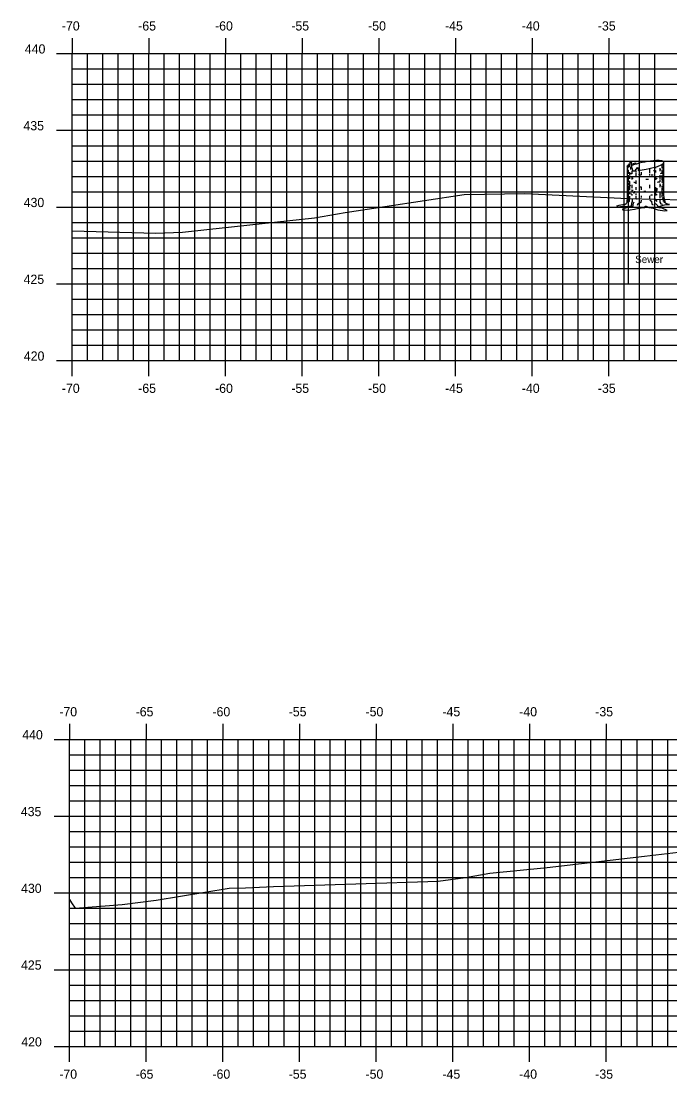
# Model space of a CAD drawing. Extents: x -161 to 764, y 111 to 210.
# Drawn here: x -161 to -118.7, y 131.7 to 200.5 of the extents above; entities that cross this region are included whole.
import ezdxf

# ---------------------------------------------------------------- set-up
doc = ezdxf.new("R2010")
doc.units = 0
for name, color, linetype in [('H_V ANNOTATION', 7, 'Continuous'), ('MAJOR', 7, 'Continuous'), ('MINOR', 7, 'Continuous'), ('S_Roadway_Centerline', 7, 'Continuous'), ('S_Trees_Decid_Pay', 7, 'Continuous'), ('S_Utilities_UG_Sanitary_Sewer', 7, 'Continuous')]:
    doc.layers.add(name, color=color, linetype=linetype)

msp = doc.modelspace()

# ---------------------------------------------------------------- linework, layer by layer
at = {"layer": 'MAJOR'}
for p, q in [((-157.693, 199.435), (-157.693, 198.433)), ((-152.693, 199.435), (-152.693, 198.433)), ((-147.693, 199.435), (-147.693, 198.433)), ((-142.693, 199.435), (-142.693, 198.433)), ((-137.693, 199.435), (-137.693, 198.433)), ((-132.693, 199.435), (-132.693, 198.433)), ((-127.693, 199.435), (-127.693, 198.433)), ((-122.693, 199.435), (-122.693, 198.433)), ((-158.695, 198.433), (-157.693, 198.433)), ((-157.693, 198.433), (-17.693, 198.433)), ((-157.693, 178.433), (-157.693, 198.433)), ((-157.693, 178.433), (-157.693, 198.433)), ((-157.693, 198.433), (-17.693, 198.433)), ((-152.693, 178.433), (-152.693, 198.433)), ((-147.693, 178.433), (-147.693, 198.433)), ((-142.693, 178.433), (-142.693, 198.433)), ((-137.693, 178.433), (-137.693, 198.433)), ((-132.693, 178.433), (-132.693, 198.433)), ((-127.693, 178.433), (-127.693, 198.433)), ((-122.693, 178.433), (-122.693, 198.433)), ((-158.695, 193.433), (-157.693, 193.433)), ((-157.693, 193.433), (-17.693, 193.433)), ((-158.695, 188.433), (-157.693, 188.433)), ((-157.693, 188.433), (-17.693, 188.433)), ((-158.695, 183.433), (-157.693, 183.433)), ((-157.693, 183.433), (-17.693, 183.433)), ((-158.695, 178.433), (-157.693, 178.433)), ((-157.693, 178.433), (-17.693, 178.433)), ((-157.693, 178.433), (-17.693, 178.433)), ((-157.693, 177.431), (-157.693, 178.433)), ((-152.693, 177.431), (-152.693, 178.433)), ((-147.693, 177.431), (-147.693, 178.433)), ((-142.693, 177.431), (-142.693, 178.433)), ((-137.693, 177.431), (-137.693, 178.433)), ((-132.693, 177.431), (-132.693, 178.433)), ((-127.693, 177.431), (-127.693, 178.433)), ((-122.693, 177.431), (-122.693, 178.433)), ((-157.863, 154.77), (-157.863, 153.768)), ((-152.863, 154.77), (-152.863, 153.768)), ((-147.863, 154.77), (-147.863, 153.768)), ((-142.863, 154.77), (-142.863, 153.768)), ((-137.863, 154.77), (-137.863, 153.768)), ((-132.863, 154.77), (-132.863, 153.768)), ((-127.863, 154.77), (-127.863, 153.768)), ((-122.863, 154.77), (-122.863, 153.768)), ((-158.865, 153.768), (-157.863, 153.768)), ((-157.863, 153.768), (-17.863, 153.768)), ((-157.863, 133.768), (-157.863, 153.768)), ((-157.863, 133.768), (-157.863, 153.768)), ((-157.863, 153.768), (-17.863, 153.768)), ((-152.863, 133.768), (-152.863, 153.768)), ((-147.863, 133.768), (-147.863, 153.768)), ((-142.863, 133.768), (-142.863, 153.768)), ((-137.863, 133.768), (-137.863, 153.768)), ((-132.863, 133.768), (-132.863, 153.768)), ((-127.863, 133.768), (-127.863, 153.768)), ((-122.863, 133.768), (-122.863, 153.768)), ((-158.865, 148.768), (-157.863, 148.768)), ((-157.863, 148.768), (-17.863, 148.768)), ((-158.865, 143.768), (-157.863, 143.768)), ((-157.863, 143.768), (-17.863, 143.768)), ((-158.865, 138.768), (-157.863, 138.768)), ((-157.863, 138.768), (-17.863, 138.768)), ((-158.865, 133.768), (-157.863, 133.768)), ((-157.863, 133.768), (-17.863, 133.768)), ((-157.863, 133.768), (-17.863, 133.768)), ((-157.863, 132.766), (-157.863, 133.768)), ((-152.863, 132.766), (-152.863, 133.768)), ((-147.863, 132.766), (-147.863, 133.768)), ((-142.863, 132.766), (-142.863, 133.768)), ((-137.863, 132.766), (-137.863, 133.768)), ((-132.863, 132.766), (-132.863, 133.768)), ((-127.863, 132.766), (-127.863, 133.768)), ((-122.863, 132.766), (-122.863, 133.768))]:
    msp.add_line(p, q, dxfattribs=at)
at = {"layer": 'MINOR'}
for p, q in [((-156.693, 178.433), (-156.693, 198.433)), ((-155.693, 178.433), (-155.693, 198.433)), ((-154.693, 178.433), (-154.693, 198.433)), ((-153.693, 178.433), (-153.693, 198.433)), ((-151.693, 178.433), (-151.693, 198.433)), ((-150.693, 178.433), (-150.693, 198.433)), ((-149.693, 178.433), (-149.693, 198.433)), ((-148.693, 178.433), (-148.693, 198.433)), ((-146.693, 178.433), (-146.693, 198.433)), ((-145.693, 178.433), (-145.693, 198.433)), ((-144.693, 178.433), (-144.693, 198.433)), ((-143.693, 178.433), (-143.693, 198.433)), ((-141.693, 178.433), (-141.693, 198.433)), ((-140.693, 178.433), (-140.693, 198.433)), ((-139.693, 178.433), (-139.693, 198.433)), ((-138.693, 178.433), (-138.693, 198.433)), ((-136.693, 178.433), (-136.693, 198.433)), ((-135.693, 178.433), (-135.693, 198.433)), ((-134.693, 178.433), (-134.693, 198.433)), ((-133.693, 178.433), (-133.693, 198.433)), ((-131.693, 178.433), (-131.693, 198.433)), ((-130.693, 178.433), (-130.693, 198.433)), ((-129.693, 178.433), (-129.693, 198.433)), ((-128.693, 178.433), (-128.693, 198.433)), ((-126.693, 178.433), (-126.693, 198.433)), ((-125.693, 178.433), (-125.693, 198.433)), ((-124.693, 178.433), (-124.693, 198.433)), ((-123.693, 178.433), (-123.693, 198.433)), ((-121.693, 178.433), (-121.693, 198.433)), ((-120.693, 178.433), (-120.693, 198.433)), ((-119.693, 178.433), (-119.693, 198.433)), ((-157.693, 197.433), (-17.693, 197.433)), ((-157.693, 197.433), (-156.691, 197.433)), ((-157.693, 196.433), (-17.693, 196.433)), ((-157.693, 196.433), (-156.691, 196.433)), ((-157.693, 195.433), (-17.693, 195.433)), ((-157.693, 195.433), (-156.691, 195.433)), ((-157.693, 194.433), (-17.693, 194.433)), ((-157.693, 194.433), (-156.691, 194.433)), ((-157.693, 192.433), (-17.693, 192.433)), ((-157.693, 192.433), (-156.691, 192.433)), ((-157.693, 191.433), (-17.693, 191.433)), ((-157.693, 191.433), (-156.691, 191.433)), ((-157.693, 190.433), (-17.693, 190.433)), ((-157.693, 190.433), (-156.691, 190.433)), ((-157.693, 189.433), (-17.693, 189.433)), ((-157.693, 189.433), (-156.691, 189.433)), ((-157.693, 187.433), (-17.693, 187.433)), ((-157.693, 187.433), (-156.691, 187.433)), ((-157.693, 186.433), (-17.693, 186.433)), ((-157.693, 186.433), (-156.691, 186.433)), ((-157.693, 185.433), (-17.693, 185.433)), ((-157.693, 185.433), (-156.691, 185.433)), ((-157.693, 184.433), (-17.693, 184.433)), ((-157.693, 184.433), (-156.691, 184.433)), ((-157.693, 182.433), (-17.693, 182.433)), ((-157.693, 182.433), (-156.691, 182.433)), ((-157.693, 181.433), (-17.693, 181.433)), ((-157.693, 181.433), (-156.691, 181.433)), ((-157.693, 180.433), (-17.693, 180.433)), ((-157.693, 180.433), (-156.691, 180.433)), ((-157.693, 179.433), (-17.693, 179.433)), ((-157.693, 179.433), (-156.691, 179.433)), ((-156.863, 133.768), (-156.863, 153.768)), ((-155.863, 133.768), (-155.863, 153.768)), ((-154.863, 133.768), (-154.863, 153.768)), ((-153.863, 133.768), (-153.863, 153.768)), ((-151.863, 133.768), (-151.863, 153.768)), ((-150.863, 133.768), (-150.863, 153.768)), ((-149.863, 133.768), (-149.863, 153.768)), ((-148.863, 133.768), (-148.863, 153.768)), ((-146.863, 133.768), (-146.863, 153.768)), ((-145.863, 133.768), (-145.863, 153.768)), ((-144.863, 133.768), (-144.863, 153.768)), ((-143.863, 133.768), (-143.863, 153.768)), ((-141.863, 133.768), (-141.863, 153.768)), ((-140.863, 133.768), (-140.863, 153.768)), ((-139.863, 133.768), (-139.863, 153.768)), ((-138.863, 133.768), (-138.863, 153.768)), ((-136.863, 133.768), (-136.863, 153.768)), ((-135.863, 133.768), (-135.863, 153.768)), ((-134.863, 133.768), (-134.863, 153.768)), ((-133.863, 133.768), (-133.863, 153.768)), ((-131.863, 133.768), (-131.863, 153.768)), ((-130.863, 133.768), (-130.863, 153.768)), ((-129.863, 133.768), (-129.863, 153.768)), ((-128.863, 133.768), (-128.863, 153.768)), ((-126.863, 133.768), (-126.863, 153.768)), ((-125.863, 133.768), (-125.863, 153.768)), ((-124.863, 133.768), (-124.863, 153.768)), ((-123.863, 133.768), (-123.863, 153.768)), ((-121.863, 133.768), (-121.863, 153.768)), ((-120.863, 133.768), (-120.863, 153.768)), ((-119.863, 133.768), (-119.863, 153.768)), ((-118.863, 133.768), (-118.863, 153.768)), ((-157.863, 152.768), (-17.863, 152.768)), ((-157.863, 152.768), (-156.861, 152.768)), ((-157.863, 151.768), (-17.863, 151.768)), ((-157.863, 151.768), (-156.861, 151.768)), ((-157.863, 150.768), (-17.863, 150.768)), ((-157.863, 150.768), (-156.861, 150.768)), ((-157.863, 149.768), (-17.863, 149.768)), ((-157.863, 149.768), (-156.861, 149.768)), ((-157.863, 147.768), (-17.863, 147.768)), ((-157.863, 147.768), (-156.861, 147.768)), ((-157.863, 146.768), (-17.863, 146.768)), ((-157.863, 146.768), (-156.861, 146.768)), ((-157.863, 145.768), (-17.863, 145.768)), ((-157.863, 145.768), (-156.861, 145.768)), ((-157.863, 144.768), (-17.863, 144.768)), ((-157.863, 144.768), (-156.861, 144.768)), ((-157.863, 142.768), (-17.863, 142.768)), ((-157.863, 142.768), (-156.861, 142.768)), ((-157.863, 141.768), (-17.863, 141.768)), ((-157.863, 141.768), (-156.861, 141.768)), ((-157.863, 140.768), (-17.863, 140.768)), ((-157.863, 140.768), (-156.861, 140.768)), ((-157.863, 139.768), (-17.863, 139.768)), ((-157.863, 139.768), (-156.861, 139.768)), ((-157.863, 137.768), (-17.863, 137.768)), ((-157.863, 137.768), (-156.861, 137.768)), ((-157.863, 136.768), (-17.863, 136.768)), ((-157.863, 136.768), (-156.861, 136.768)), ((-157.863, 135.768), (-17.863, 135.768)), ((-157.863, 135.768), (-156.861, 135.768)), ((-157.863, 134.768), (-17.863, 134.768)), ((-157.863, 134.768), (-156.861, 134.768))]:
    msp.add_line(p, q, dxfattribs=at)
at = {"layer": 'S_Roadway_Centerline'}
for points in [[(-157.693, 186.896), (-152.22, 186.735), (-150.498, 186.807), (-148.901, 186.975), (-141.893, 187.734), (-139.882, 188.09), (-132.124, 189.256), (-128.171, 189.315), (-121.467, 188.992), (-115.974, 188.872), (-110.769, 188.6), (-96.239, 188.433), (-93.99, 188.538), (-87.1, 188.918), (-86.065, 188.968), (-75.289, 189.172), (-68.973, 189.373), (-42.532, 188.98), (-34.493, 188.828), (-32.191, 188.81), (-29.47, 188.805), (-17.693, 188.431)], [(-157.863, 143.341), (-157.723, 143.12), (-157.491, 142.781), (-154.413, 143.007), (-152.205, 143.302), (-147.459, 144.078), (-146.374, 144.11), (-144.561, 144.195), (-133.827, 144.541), (-132.039, 144.763), (-130.463, 145.049), (-126.715, 145.433), (-120.377, 146.165), (-117.425, 146.515), (-117.256, 146.518), (-109.618, 146.417), (-104.371, 146.317), (-104.168, 146.321), (-87.565, 146.329), (-83.22, 146.326), (-80.412, 146.295), (-73.107, 146.205)]]:
    msp.add_lwpolyline(points, dxfattribs=at)
at = {"layer": 'S_Trees_Decid_Pay'}
for p, q in [((-121.446, 190.854), (-121.446, 190.599)), ((-121.296, 191.054), (-121.296, 190.88)), ((-121.211, 190.805), (-121.211, 190.601)), ((-120.95, 190.807), (-120.95, 190.688)), ((-120.039, 190.945), (-120.039, 190.665)), ((-119.656, 191.046), (-119.656, 190.96)), ((-119.656, 190.819), (-119.656, 190.679)), ((-119.384, 190.96), (-119.384, 190.768)), ((-119.251, 191.213), (-119.251, 190.96)), ((-119.251, 190.863), (-119.251, 190.599)), ((-119.171, 191.258), (-119.171, 191.137)), ((-119.171, 191.085), (-119.171, 190.871)), ((-119.171, 190.826), (-119.171, 190.488)), ((-121.446, 190.502), (-121.446, 190.033)), ((-121.36, 190.708), (-121.36, 190.496)), ((-121.36, 190.431), (-121.36, 190.282)), ((-121.211, 190.393), (-121.211, 190.239)), ((-120.95, 190.636), (-120.95, 190.451)), ((-120.95, 190.165), (-120.95, 189.937)), ((-120.712, 190.536), (-120.707, 190.643)), ((-120.585, 190.708), (-120.585, 190.529)), ((-120.039, 190.599), (-120.039, 190.496)), ((-119.656, 190.393), (-119.656, 190.202)), ((-119.384, 190.517), (-119.384, 190.239)), ((-119.384, 190.194), (-119.384, 190.085)), ((-119.251, 190.502), (-119.251, 190.194)), ((-119.171, 190.371), (-119.171, 190.01)), ((-121.446, 189.982), (-121.446, 189.848)), ((-121.446, 189.79), (-121.446, 189.465)), ((-121.446, 189.436), (-121.446, 189.016)), ((-121.36, 190.105), (-121.36, 189.805)), ((-121.36, 189.767), (-121.36, 189.525)), ((-121.211, 189.876), (-121.211, 189.657)), ((-121.211, 189.557), (-121.211, 189.436)), ((-120.95, 189.739), (-120.95, 189.553)), ((-120.585, 189.75), (-120.585, 189.553)), ((-120.039, 189.885), (-120.039, 189.664)), ((-119.656, 189.722), (-119.656, 189.514)), ((-119.384, 189.95), (-119.384, 189.722)), ((-119.251, 190.105), (-119.251, 190.039)), ((-119.251, 189.805), (-119.251, 189.708)), ((-119.251, 189.657), (-119.251, 189.296)), ((-119.171, 189.973), (-119.171, 189.525)), ((-119.171, 189.459), (-119.171, 189.177)), ((-121.442, 188.913), (-121.457, 188.796)), ((-121.36, 189.414), (-121.36, 189.273)), ((-121.36, 189.141), (-121.36, 188.985)), ((-121.211, 189.285), (-121.211, 189.187)), ((-120.95, 189.319), (-120.95, 189.242)), ((-120.95, 189.164), (-120.95, 188.991)), ((-120.585, 189.17), (-120.585, 189.067)), ((-120.039, 189.164), (-120.039, 188.991)), ((-119.661, 188.936), (-119.581, 188.804)), ((-119.656, 189.393), (-119.656, 189.193)), ((-119.384, 189.393), (-119.384, 189.01)), ((-119.251, 189.244), (-119.251, 189.078))]:
    msp.add_line(p, q, dxfattribs=at)
for points in [[(-121.496, 191.128), (-121.496, 188.991), (-121.516, 188.849), (-121.522, 188.723), (-121.566, 188.637), (-121.658, 188.588), (-121.794, 188.588), (-122.037, 188.532), (-122.204, 188.483), (-122.062, 188.452), (-121.825, 188.489), (-121.615, 188.477), (-121.354, 188.483), (-121.23, 188.501), (-121.2, 188.458), (-121.137, 188.501), (-121.236, 188.433), (-121.471, 188.408), (-121.701, 188.347), (-121.831, 188.277), (-121.732, 188.233), (-121.31, 188.252), (-121.032, 188.296), (-120.734, 188.372), (-120.448, 188.408), (-120.343, 188.408), (-120.324, 188.489), (-120.256, 188.495), (-120.089, 188.408), (-119.803, 188.353), (-119.505, 188.246), (-119.045, 188.197), (-118.891, 188.209), (-119.233, 188.359), (-119.436, 188.39), (-119.425, 188.464), (-119.165, 188.563), (-118.99, 188.594), (-118.749, 188.606), (-118.947, 188.643), (-119.009, 188.68), (-119.033, 188.767), (-119.045, 188.936), (-119.091, 189.022), (-119.119, 189.263), (-119.119, 191.349)], [(-121.14, 190.801), (-121.148, 190.945), (-121.193, 190.937), (-121.207, 191.312), (-121.302, 191.32), (-121.316, 191.4), (-121.354, 191.063), (-121.399, 191.157), (-121.419, 191.003), (-121.496, 191.128), (-121.49, 190.939)], [(-121.496, 191.128), (-121.45, 191.151), (-121.428, 191.217), (-121.376, 191.24), (-121.343, 191.165)], [(-121.117, 191.167), (-121.096, 191.275), (-120.965, 191.305), (-120.957, 191.218)], [(-120.978, 190.805), (-120.942, 190.908), (-120.876, 190.914), (-120.876, 190.996), (-120.802, 191.003), (-120.777, 190.823)], [(-121.088, 189.436), (-121.096, 189.362), (-121.022, 189.356), (-121.008, 189.473)], [(-119.543, 189.528), (-119.544, 189.605), (-119.552, 189.671)], [(-121.376, 188.921), (-121.383, 188.796), (-121.465, 188.701)], [(-121.23, 188.501), (-121.211, 188.68), (-121.15, 188.817), (-121.156, 188.917)], [(-121.039, 188.748), (-121.113, 188.68), (-121.131, 188.582), (-121.137, 188.501)], [(-120.587, 188.884), (-120.604, 188.73), (-120.802, 188.649), (-120.847, 188.546)], [(-120.022, 188.876), (-119.919, 188.824), (-119.904, 188.618), (-119.801, 188.59)], [(-119.367, 188.95), (-119.367, 188.744), (-119.309, 188.635), (-119.212, 188.618)], [(-119.226, 189.024), (-119.155, 188.921), (-119.155, 188.796)], [(-119.169, 189.105), (-119.109, 188.944), (-119.095, 188.819), (-119.103, 188.721)], [(-119.436, 188.39), (-119.523, 188.532), (-119.655, 188.674)]]:
    msp.add_lwpolyline(points, dxfattribs=at)
for centre, radius, start, end in [((-120.686, 189.941), 1.299, 107.86134, 113.3069), ((-119.206, 185.347), 6.126, 100.77788, 107.86134), ((-121.408, 196.916), 6.126, 273.69441, 274.02462), ((-121.408, 196.916), 6.126, 275.91473, 280.77788), ((-119.206, 185.347), 6.126, 93.69441, 100.77788), ((-121.408, 196.916), 6.126, 280.77788, 287.86134), ((-120.306, 196.699), 5.916, 274.95145, 276.30875), ((-119.517, 190.164), 1.299, 78.27788, 93.69441), ((-119.928, 192.322), 1.299, 287.86134, 303.27788), ((-119.73, 192.111), 1.292, 285.56512, 289.09156), ((-119.351, 190.966), 0.48, 69.98432, 78.27788), ((-119.478, 191.637), 0.48, 303.27788, 311.57144), ((-119.243, 191.263), 0.164, 55.77788, 69.98432), ((-119.258, 191.092), 0.166, 301.67004, 315), ((-119.269, 191.401), 0.164, 311.57144, 325.77788), ((-119.211, 191.31), 0.107, 45.9547, 55.77788), ((-119.218, 191.051), 0.109, 315, 324.82628), ((-119.181, 191.34), 0.0645, 33.27788, 45.9547), ((-119.222, 191.369), 0.107, 325.77788, 335.60106), ((-119.182, 191.026), 0.0657, 324.82628, 337.5), ((-119.173, 191.346), 0.0544, 22.46002, 33.27788), ((-119.183, 191.351), 0.0645, 335.60106, 348.27788), ((-119.165, 191.349), 0.0467, 10.77788, 22.46002), ((-119.173, 191.022), 0.0554, 337.5, 348.31854), ((-119.173, 191.349), 0.0544, 348.27788, 359.09574), ((-119.165, 191.349), 0.0467, 359.09574, 10.77788), ((-121.448, 190.76), 0.0476, 180, 191.68146), ((-121.448, 190.239), 0.0476, 180, 191.68146), ((-121.441, 190.762), 0.0554, 191.68146, 202.5), ((-121.441, 190.241), 0.0554, 191.68146, 202.5), ((-121.431, 190.765), 0.0657, 202.5, 215.17372), ((-121.431, 190.245), 0.0657, 202.5, 215.17372), ((-121.396, 190.79), 0.109, 215.17372, 225), ((-121.396, 190.27), 0.109, 215.17372, 225), ((-121.355, 190.831), 0.166, 225, 239.19244), ((-121.355, 190.31), 0.166, 225, 239.19244), ((-121.355, 190.567), 0.166, 237.03779, 239.19244), ((-121.192, 190.84), 0.484, 239.19244, 247.5), ((-121.192, 190.583), 0.484, 239.19244, 245.77245), ((-120.883, 191.587), 1.292, 247.5, 248.35373), ((-120.883, 191.329), 1.292, 247.5, 248.48417), ((-120.883, 191.85), 1.292, 250.61187, 255.28558), ((-120.883, 191.587), 1.292, 255.28558, 259.26323), ((-121.097, 192.1), 1.299, 268.12894, 273.69441), ((-120.307, 196.438), 5.916, 266.07764, 267.30434), ((-120.307, 196.175), 5.916, 270.1162, 271.77083), ((-120.307, 196.438), 5.916, 273.53821, 274.89239), ((-120.307, 196.175), 5.916, 276.31835, 277.15462), ((-119.731, 191.587), 1.292, 277.15462, 278.36619), ((-119.731, 191.85), 1.292, 288.08294, 292.5), ((-119.731, 191.587), 1.292, 291.8071, 292.5), ((-119.422, 190.84), 0.484, 292.5, 300.80756), ((-119.422, 190.583), 0.484, 294.63721, 300.80756), ((-119.422, 191.104), 0.484, 297.41617, 300.80756), ((-119.259, 190.831), 0.166, 300.80756, 315), ((-119.259, 190.567), 0.166, 300.80756, 301.6001), ((-119.259, 190.31), 0.166, 300.80756, 315), ((-119.219, 190.79), 0.109, 315, 324.82628), ((-119.219, 190.27), 0.109, 315, 324.82628), ((-119.183, 190.765), 0.0657, 324.82628, 337.5), ((-119.183, 190.245), 0.0657, 324.82628, 337.5), ((-119.174, 190.762), 0.0554, 337.5, 348.31854), ((-119.174, 190.241), 0.0554, 337.5, 348.31854), ((-121.448, 189.982), 0.0476, 180, 191.68146), ((-121.448, 189.716), 0.0476, 180, 191.68146), ((-121.441, 189.983), 0.0554, 191.68146, 202.5), ((-121.441, 189.718), 0.0554, 191.68146, 202.5), ((-121.431, 189.987), 0.0657, 202.5, 215.17372), ((-121.431, 189.722), 0.0657, 202.5, 215.17372), ((-121.396, 190.012), 0.109, 215.17372, 225), ((-121.396, 189.747), 0.109, 215.17372, 225), ((-121.355, 190.053), 0.166, 225, 239.19244), ((-121.355, 189.787), 0.166, 225, 239.19244), ((-121.192, 190.06), 0.484, 239.19244, 247.5), ((-120.883, 191.072), 1.292, 247.5, 251.79898), ((-120.883, 190.806), 1.292, 247.5, 248.35373), ((-120.883, 190.806), 1.292, 255.28558, 259.24628), ((-120.883, 191.329), 1.292, 261.87257, 262.84537), ((-120.307, 195.917), 5.916, 262.84537, 263.7595), ((-120.307, 195.66), 5.916, 266.27211, 267.30434), ((-120.307, 195.394), 5.916, 268.92065, 270), ((-120.307, 195.394), 5.916, 270, 270.27568), ((-120.307, 195.394), 5.916, 276.31835, 277.15462), ((-119.731, 190.806), 1.292, 277.15462, 278.37952), ((-119.731, 191.329), 1.292, 279.25654, 285.6105), ((-119.731, 191.072), 1.292, 285.61049, 290.10015), ((-119.422, 190.06), 0.484, 292.5, 300.80756), ((-119.259, 189.787), 0.166, 300.80756, 302.06939), ((-119.259, 190.053), 0.166, 302.06939, 315), ((-119.219, 190.012), 0.109, 315, 324.82628), ((-119.183, 189.987), 0.0657, 324.82628, 337.5), ((-119.174, 189.983), 0.0554, 337.5, 348.31854), ((-119.174, 189.718), 0.0554, 337.5, 348.31854), ((-119.174, 189.446), 0.0554, 337.5, 348.31854), ((-121.448, 189.187), 0.0476, 180, 191.68146), ((-121.441, 189.188), 0.0554, 191.68146, 202.5), ((-121.431, 189.192), 0.0657, 202.5, 215.17372), ((-121.396, 189.217), 0.109, 215.17372, 225), ((-121.355, 189.258), 0.166, 225, 239.19244), ((-121.192, 189.531), 0.484, 239.19244, 247.5), ((-121.192, 189.788), 0.484, 242.73401, 247.5), ((-120.883, 190.277), 1.292, 247.5, 248.35373), ((-120.883, 190.535), 1.292, 251.36642, 255.28558), ((-120.307, 194.865), 5.916, 263.78314, 264.76555), ((-120.307, 195.123), 5.916, 273.26366, 274.46102), ((-120.307, 195.123), 5.916, 276.31835, 277.15462), ((-119.731, 190.535), 1.292, 277.15462, 278.36619), ((-119.731, 190.535), 1.292, 285.61049, 289.15336), ((-119.722, 190.281), 1.292, 291.36963, 292.0604), ((-119.422, 189.531), 0.484, 292.5, 296.54992), ((-119.259, 189.515), 0.166, 302.06939, 315), ((-119.219, 189.475), 0.109, 315, 324.82628), ((-119.183, 189.45), 0.0657, 324.82628, 337.5)]:
    msp.add_arc(centre, radius, start, end, dxfattribs=at)
at = {"layer": 'S_Utilities_UG_Sanitary_Sewer'}
msp.add_line((-121.432, 188.957), (-121.432, 183.421), dxfattribs=at)

# ---------------------------------------------------------------- texts
at = {"layer": 'H_V ANNOTATION'}
for s, p in [('-70', (-158.352, 199.933)), ('-65', (-153.376, 199.933)), ('-60', (-148.368, 199.933)), ('-55', (-143.397, 199.933)), ('-50', (-138.389, 199.933)), ('-45', (-133.376, 199.933)), ('-40', (-128.368, 199.933)), ('-35', (-123.413, 199.933)), ('440', (-160.767, 198.433)), ('435', (-160.858, 193.433)), ('430', (-160.842, 188.433)), ('425', (-160.847, 183.433)), ('420', (-160.831, 178.433)), ('-70', (-158.352, 176.333)), ('-65', (-153.376, 176.333)), ('-60', (-148.368, 176.333)), ('-55', (-143.397, 176.333)), ('-50', (-138.389, 176.333)), ('-45', (-133.376, 176.333)), ('-40', (-128.368, 176.333)), ('-35', (-123.413, 176.333))]:
    msp.add_text(s, height=0.6, rotation=360, dxfattribs=at).set_placement(p)
for s, p in [('-70', (-158.522, 155.268)), ('-65', (-153.546, 155.268)), ('-60', (-148.538, 155.268)), ('-55', (-143.567, 155.268)), ('-50', (-138.559, 155.268)), ('-45', (-133.546, 155.268)), ('-40', (-128.538, 155.268)), ('-35', (-123.583, 155.268)), ('440', (-160.937, 153.768)), ('435', (-161.028, 148.768)), ('430', (-161.012, 143.768)), ('425', (-161.017, 138.768)), ('420', (-161.001, 133.768)), ('-70', (-158.522, 131.668)), ('-65', (-153.546, 131.668)), ('-60', (-148.538, 131.668)), ('-55', (-143.567, 131.668)), ('-50', (-138.559, 131.668)), ('-45', (-133.546, 131.668)), ('-40', (-128.538, 131.668)), ('-35', (-123.583, 131.668))]:
    msp.add_text(s, height=0.6, dxfattribs=at).set_placement(p)
at = {"layer": 'MAJOR'}
for height, p in [(1.5248952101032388e-17, (-157.698, 178.433)), (1.491634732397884e-17, (-157.868, 133.768))]:
    msp.add_text('-', height=height, rotation=53.1301, dxfattribs=at).set_placement(p)
at = {"layer": 'S_Utilities_UG_Sanitary_Sewer'}
msp.add_text('Sewer', height=0.4798, rotation=360, dxfattribs=at).set_placement((-120.981, 184.786))

doc.saveas('drawing.dxf')
